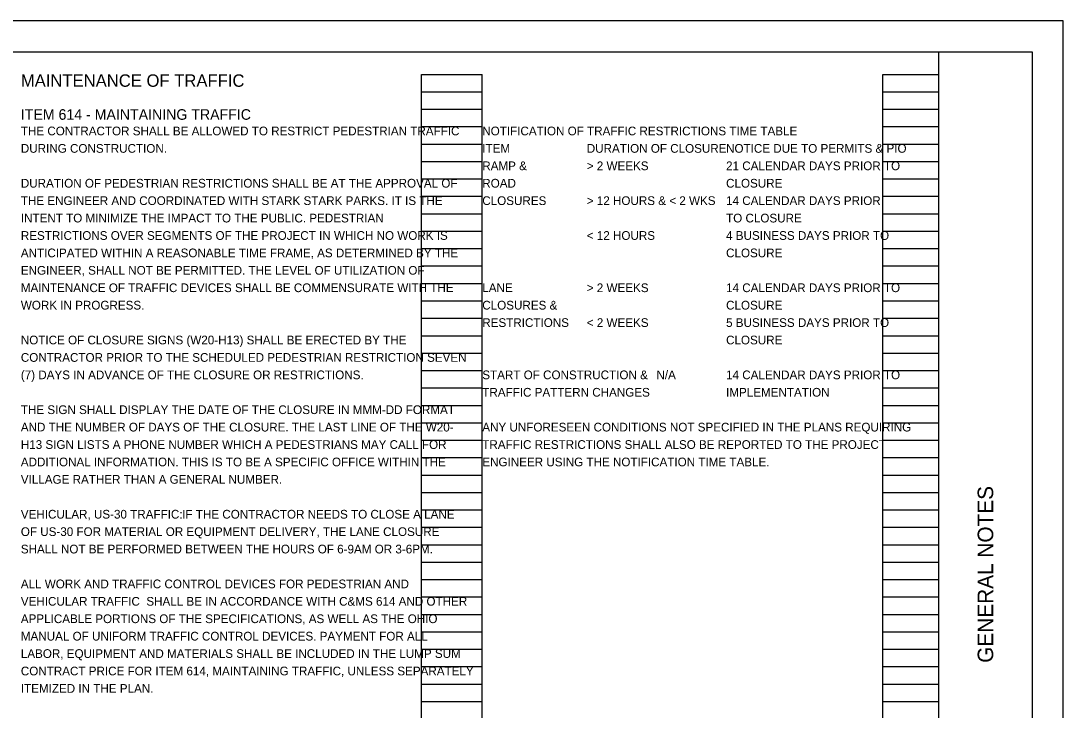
# Model space of a CAD drawing. Extents: x 0 to 34, y 0 to 22.
# Drawn here: x 17.24 to 34, y 10.92 to 22 of the extents above; entities that cross this region are included whole.
import ezdxf

# ---------------------------------------------------------------- set-up
doc = ezdxf.new("R2010")
doc.units = 0
for name, color, linetype in [('SH_Border', 7, 'Continuous'), ('SH_Cut_Line', 7, 'Continuous'), ('SH_Data', 7, 'Continuous'), ('SH_Text', 7, 'Continuous')]:
    doc.layers.add(name, color=color, linetype=linetype)

msp = doc.modelspace()

# ---------------------------------------------------------------- linework, layer by layer
at = {"layer": 'SH_Border'}
msp.add_line((32, 0.5), (32, 21.5), dxfattribs=at)
msp.add_lwpolyline([(1.5, 21.5), (33.5, 21.5), (33.5, 0.5), (1.5, 0.5)], close=True, dxfattribs=at)
at = {"layer": 'SH_Cut_Line'}
msp.add_lwpolyline([(0, 0), (34, 0), (34, 22), (0, 22)], close=True, dxfattribs=at)
at = {"layer": 'SH_Data'}
for p, q in [((23.68, 0.98), (23.68, 21.14)), ((23.68, 21.14), (24.66, 21.14)), ((24.66, 0.98), (24.66, 21.14)), ((31.1, 0.98), (31.1, 21.14)), ((31.1, 21.14), (32, 21.14)), ((32, 0.98), (32, 21.14)), ((23.68, 20.86), (24.66, 20.86)), ((31.1, 20.86), (32, 20.86)), ((23.68, 20.58), (24.66, 20.58)), ((31.1, 20.58), (32, 20.58)), ((23.68, 20.3), (24.66, 20.3)), ((31.1, 20.3), (32, 20.3)), ((23.68, 20.02), (24.66, 20.02)), ((31.1, 20.02), (32, 20.02)), ((23.68, 19.74), (24.66, 19.74)), ((31.1, 19.74), (32, 19.74)), ((23.68, 19.46), (24.66, 19.46)), ((31.1, 19.46), (32, 19.46)), ((23.68, 19.18), (24.66, 19.18)), ((31.1, 19.18), (32, 19.18)), ((23.68, 18.9), (24.66, 18.9)), ((31.1, 18.9), (32, 18.9)), ((23.68, 18.62), (24.66, 18.62)), ((31.1, 18.62), (32, 18.62)), ((23.68, 18.34), (24.66, 18.34)), ((31.1, 18.34), (32, 18.34)), ((23.68, 18.06), (24.66, 18.06)), ((31.1, 18.06), (32, 18.06)), ((23.68, 17.78), (24.66, 17.78)), ((31.1, 17.78), (32, 17.78)), ((23.68, 17.5), (24.66, 17.5)), ((31.1, 17.5), (32, 17.5)), ((23.68, 17.22), (24.66, 17.22)), ((31.1, 17.22), (32, 17.22)), ((23.68, 16.94), (24.66, 16.94)), ((31.1, 16.94), (32, 16.94)), ((23.68, 16.66), (24.66, 16.66)), ((31.1, 16.66), (32, 16.66)), ((23.68, 16.38), (24.66, 16.38)), ((31.1, 16.38), (32, 16.38)), ((23.68, 16.1), (24.66, 16.1)), ((31.1, 16.1), (32, 16.1)), ((23.68, 15.82), (24.66, 15.82)), ((31.1, 15.82), (32, 15.82)), ((23.68, 15.54), (24.66, 15.54)), ((31.1, 15.54), (32, 15.54)), ((23.68, 15.26), (24.66, 15.26)), ((31.1, 15.26), (32, 15.26)), ((23.68, 14.98), (24.66, 14.98)), ((31.1, 14.98), (32, 14.98)), ((23.68, 14.7), (24.66, 14.7)), ((31.1, 14.7), (32, 14.7)), ((23.68, 14.42), (24.66, 14.42)), ((31.1, 14.42), (32, 14.42)), ((23.68, 14.14), (24.66, 14.14)), ((31.1, 14.14), (32, 14.14)), ((23.68, 13.86), (24.66, 13.86)), ((31.1, 13.86), (32, 13.86)), ((23.68, 13.58), (24.66, 13.58)), ((31.1, 13.58), (32, 13.58)), ((23.68, 13.3), (24.66, 13.3)), ((31.1, 13.3), (32, 13.3)), ((23.68, 13.02), (24.66, 13.02)), ((31.1, 13.02), (32, 13.02)), ((23.68, 12.74), (24.66, 12.74)), ((31.1, 12.74), (32, 12.74)), ((23.68, 12.46), (24.66, 12.46)), ((31.1, 12.46), (32, 12.46)), ((23.68, 12.18), (24.66, 12.18)), ((31.1, 12.18), (32, 12.18)), ((23.68, 11.9), (24.66, 11.9)), ((31.1, 11.9), (32, 11.9)), ((23.68, 11.62), (24.66, 11.62)), ((31.1, 11.62), (32, 11.62)), ((23.68, 11.34), (24.66, 11.34)), ((31.1, 11.34), (32, 11.34)), ((23.68, 11.06), (24.66, 11.06)), ((31.1, 11.06), (32, 11.06))]:
    msp.add_line(p, q, dxfattribs=at)

# ---------------------------------------------------------------- texts
msp.add_text('GENERAL NOTES', height=0.25, rotation=90, dxfattribs=at).set_placement((32.875, 11.682))
at = {"layer": 'SH_Text'}
for s, height, p in [('MAINTENANCE OF TRAFFIC', 0.2, (17.24, 20.94)), ('ITEM 614 - MAINTAINING TRAFFIC', 0.17, (17.24, 20.41)), ('THE CONTRACTOR SHALL BE ALLOWED TO RESTRICT PEDESTRIAN TRAFFIC ', 0.14, (17.24, 20.16)), ('NOTIFICATION OF TRAFFIC RESTRICTIONS TIME TABLE', 0.14, (24.66, 20.16)), ('DURING CONSTRUCTION.', 0.14, (17.24, 19.88)), ('ITEM', 0.14, (24.66, 19.88)), ('DURATION OF CLOSURE', 0.14, (26.34, 19.88)), ('NOTICE DUE TO PERMITS & PIO', 0.14, (28.58, 19.88)), ('RAMP &', 0.14, (24.66, 19.6)), ('> 2 WEEKS', 0.14, (26.34, 19.6)), ('21 CALENDAR DAYS PRIOR TO', 0.14, (28.58, 19.6)), ('DURATION OF PEDESTRIAN RESTRICTIONS SHALL BE AT THE APPROVAL OF ', 0.14, (17.24, 19.32)), ('ROAD', 0.14, (24.66, 19.32)), ('CLOSURE', 0.14, (28.58, 19.32)), ('THE ENGINEER AND COORDINATED WITH STARK STARK PARKS. IT IS THE ', 0.14, (17.24, 19.04)), ('CLOSURES', 0.14, (24.66, 19.04)), ('> 12 HOURS & < 2 WKS', 0.14, (26.34, 19.04)), ('14 CALENDAR DAYS PRIOR ', 0.14, (28.58, 19.04)), ('INTENT TO MINIMIZE THE IMPACT TO THE PUBLIC. PEDESTRIAN ', 0.14, (17.24, 18.76)), ('TO CLOSURE', 0.14, (28.58, 18.76)), ('RESTRICTIONS OVER SEGMENTS OF THE PROJECT IN WHICH NO WORK IS ', 0.14, (17.24, 18.48)), ('< 12 HOURS', 0.14, (26.34, 18.48)), ('4 BUSINESS DAYS PRIOR TO', 0.14, (28.58, 18.48)), ('ANTICIPATED WITHIN A REASONABLE TIME FRAME, AS DETERMINED BY THE ', 0.14, (17.24, 18.2)), ('CLOSURE', 0.14, (28.58, 18.2)), ('ENGINEER, SHALL NOT BE PERMITTED. THE LEVEL OF UTILIZATION OF ', 0.14, (17.24, 17.92)), ('MAINTENANCE OF TRAFFIC DEVICES SHALL BE COMMENSURATE WITH THE ', 0.14, (17.24, 17.64)), ('LANE', 0.14, (24.66, 17.64)), ('> 2 WEEKS', 0.14, (26.34, 17.64)), ('14 CALENDAR DAYS PRIOR TO', 0.14, (28.58, 17.64)), ('WORK IN PROGRESS.', 0.14, (17.24, 17.36)), ('CLOSURES &', 0.14, (24.66, 17.36)), ('CLOSURE', 0.14, (28.58, 17.36)), ('RESTRICTIONS', 0.14, (24.66, 17.08)), ('< 2 WEEKS', 0.14, (26.34, 17.08)), ('5 BUSINESS DAYS PRIOR TO', 0.14, (28.58, 17.08)), ('NOTICE OF CLOSURE SIGNS (W20-H13) SHALL BE ERECTED BY THE ', 0.14, (17.24, 16.8)), ('CLOSURE', 0.14, (28.58, 16.8)), ('CONTRACTOR PRIOR TO THE SCHEDULED PEDESTRIAN RESTRICTION SEVEN ', 0.14, (17.24, 16.52)), ('(7) DAYS IN ADVANCE OF THE CLOSURE OR RESTRICTIONS.', 0.14, (17.24, 16.24)), ('START OF CONSTRUCTION &', 0.14, (24.66, 16.24)), ('N/A', 0.14, (27.46, 16.24)), ('14 CALENDAR DAYS PRIOR TO', 0.14, (28.58, 16.24)), ('TRAFFIC PATTERN CHANGES', 0.14, (24.66, 15.96)), ('IMPLEMENTATION', 0.14, (28.58, 15.96)), ('THE SIGN SHALL DISPLAY THE DATE OF THE CLOSURE IN MMM-DD FORMAT ', 0.14, (17.24, 15.68)), ('AND THE NUMBER OF DAYS OF THE CLOSURE. THE LAST LINE OF THE W20-', 0.14, (17.24, 15.4)), ('ANY UNFORESEEN CONDITIONS NOT SPECIFIED IN THE PLANS REQUIRING ', 0.14, (24.66, 15.4)), ('H13 SIGN LISTS A PHONE NUMBER WHICH A PEDESTRIANS MAY CALL FOR ', 0.14, (17.24, 15.12)), ('TRAFFIC RESTRICTIONS SHALL ALSO BE REPORTED TO THE PROJECT ', 0.14, (24.66, 15.12)), ('ADDITIONAL INFORMATION. THIS IS TO BE A SPECIFIC OFFICE WITHIN THE ', 0.14, (17.24, 14.84)), ('ENGINEER USING THE NOTIFICATION TIME TABLE.', 0.14, (24.66, 14.84)), ('VILLAGE RATHER THAN A GENERAL NUMBER. ', 0.14, (17.24, 14.56)), ('VEHICULAR, US-30 TRAFFIC:', 0.14, (17.24, 14)), (' IF THE CONTRACTOR NEEDS TO CLOSE A LANE ', 0.14, (19.783, 14)), ('OF US-30 FOR MATERIAL OR EQUIPMENT DELIVERY, THE LANE CLOSURE ', 0.14, (17.24, 13.72)), ('SHALL NOT BE PERFORMED BETWEEN THE HOURS OF 6-9AM OR 3-6PM.', 0.14, (17.24, 13.44)), ('ALL WORK AND TRAFFIC CONTROL DEVICES FOR PEDESTRIAN AND ', 0.14, (17.24, 12.88)), ('VEHICULAR TRAFFIC  SHALL BE IN ACCORDANCE WITH C&MS 614 AND OTHER ', 0.14, (17.24, 12.6)), ('APPLICABLE PORTIONS OF THE SPECIFICATIONS, AS WELL AS THE OHIO ', 0.14, (17.24, 12.32)), ('MANUAL OF UNIFORM TRAFFIC CONTROL DEVICES. PAYMENT FOR ALL ', 0.14, (17.24, 12.04)), ('LABOR, EQUIPMENT AND MATERIALS SHALL BE INCLUDED IN THE LUMP SUM ', 0.14, (17.24, 11.76)), ('CONTRACT PRICE FOR ITEM 614, MAINTAINING TRAFFIC, UNLESS SEPARATELY ', 0.14, (17.24, 11.48)), ('ITEMIZED IN THE PLAN.', 0.14, (17.24, 11.2))]:
    msp.add_text(s, height=height, dxfattribs=at).set_placement(p)

doc.saveas('drawing.dxf')
